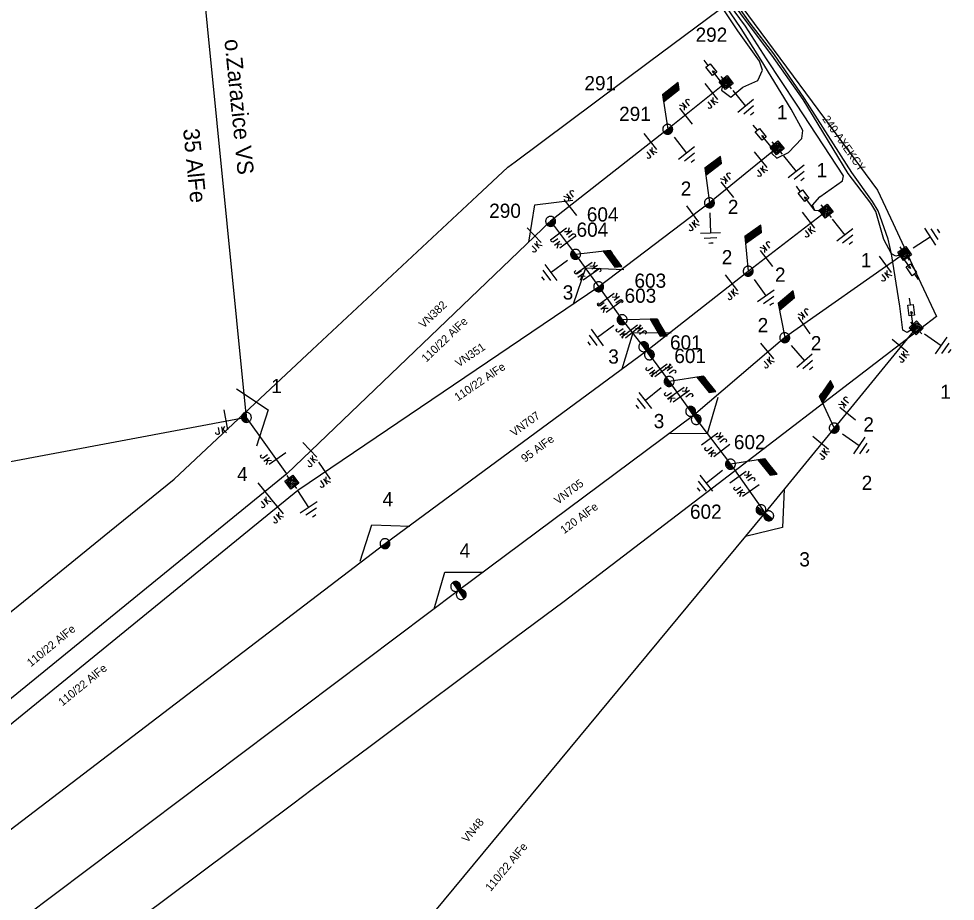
# Model space of a CAD drawing. Extents: x -545588 to -543214, y -1196037 to -1194452.
# Drawn here: x -545323.7 to -545208.3, y -1195024.5 to -1194915.7 of the extents above; entities that cross this region are included whole.
import ezdxf

# ---------------------------------------------------------------- set-up
doc = ezdxf.new("R2010")
doc.units = 0
for name, color, linetype in [('Default', 7, 'Continuous'), ('Vrstva 1', 7, 'Continuous'), ('Vrstva 11', 7, 'Continuous'), ('Vrstva 12', 7, 'Continuous'), ('Vrstva 13', 7, 'Continuous'), ('Vrstva 14', 7, 'Continuous'), ('Vrstva 15', 7, 'Continuous'), ('Vrstva 16', 7, 'Continuous'), ('Vrstva 18', 7, 'Continuous'), ('Vrstva 19', 7, 'Continuous'), ('Vrstva 2', 7, 'Continuous'), ('Vrstva 3', 7, 'Continuous'), ('Vrstva 35', 7, 'Continuous'), ('Vrstva 4', 7, 'Continuous'), ('Vrstva 5', 7, 'Continuous'), ('Vrstva 52', 7, 'Continuous'), ('Vrstva 53', 7, 'Continuous'), ('Vrstva 54', 7, 'Continuous'), ('Vrstva 6', 7, 'Continuous')]:
    doc.layers.add(name, color=color, linetype=linetype)

# ---------------------------------------------------------------- blocks, each defined once
blk = doc.blocks.new('VN840')
at = {"layer": 'Vrstva 15'}
for points in [[(-0.01, 1.41), (-0.01, -1.09)], [(-1.51, -1.24), (-1.51, -1.15)], [(-1.09, -0.59), (-1.09, -1.24)], [(-0.68, -0.59), (-0.68, -1.42)], [(-0.68, -1.11), (-0.27, -0.59)], [(-0.54, -0.94), (-0.2, -1.42)], [(-1.48, -1.35), (-1.51, -1.24)], [(-1.33, -1.42), (-1.48, -1.35)], [(-1.27, -1.42), (-1.33, -1.42)], [(-1.13, -1.35), (-1.27, -1.42)], [(-1.09, -1.24), (-1.13, -1.35)]]:
    blk.add_lwpolyline(points, dxfattribs=at)
blk = doc.blocks.new('VN860')
at = {"layer": 'Vrstva 15'}
for points in [[(-3.74, 0), (0.01, 2.82)], [(0.01, 2.82), (3.76, 0)]]:
    blk.add_lwpolyline(points, dxfattribs=at)
blk = doc.blocks.new('VN440')
at = {"layer": 'Vrstva 2'}
for points in [[(1.22, 0), (1.21, 0.13), (1.19, 0.25), (1.16, 0.38), (1.11, 0.5), (1.05, 0.61), (0.98, 0.72), (0.9, 0.82), (0.81, 0.91), (0.71, 0.99), (0.6, 1.06), (0.49, 1.12), (0.37, 1.16), (0.25, 1.2), (0.12, 1.22), (-0.01, 1.22), (-0.14, 1.22), (-0.26, 1.2), (-0.39, 1.16), (-0.51, 1.12), (-0.62, 1.06), (-0.73, 0.99), (-0.83, 0.91), (-0.92, 0.82), (-1, 0.72), (-1.07, 0.61), (-1.13, 0.5), (-1.18, 0.38), (-1.21, 0.25), (-1.23, 0.13), (-1.24, 0), (-1.23, -0.13), (-1.21, -0.26), (-1.18, -0.38), (-1.13, -0.5), (-1.07, -0.62), (-1, -0.73), (-0.92, -0.83), (-0.83, -0.92), (-0.73, -1), (-0.62, -1.07), (-0.51, -1.13), (-0.39, -1.17), (-0.26, -1.2), (-0.14, -1.23), (-0.01, -1.23), (0.12, -1.23), (0.25, -1.2), (0.37, -1.17), (0.49, -1.13), (0.6, -1.07), (0.71, -1), (0.81, -0.92), (0.9, -0.83), (0.98, -0.73), (1.05, -0.62), (1.11, -0.5), (1.16, -0.38), (1.19, -0.26), (1.21, -0.13), (1.22, 0)], [(-1.24, 0), (1.22, 0)], [(-1.18, -0.34), (1.1, -0.34)], [(-1.01, -0.63), (0.97, -0.63)], [(-0.74, -0.92), (0.68, -0.92)]]:
    blk.add_lwpolyline(points, dxfattribs=at)
blk = doc.blocks.new('VN890')
at = {"layer": 'Vrstva 4'}
for points in [[(-0.41, 0.41), (0.41, 0)], [(-0.41, -0.41), (-0.41, 0.41)], [(0.41, 0), (-0.41, -0.41)], [(-0.34, 0.31), (0.27, 0), (-0.34, -0.3), (-0.34, 0.31)], [(-0.26, 0.2), (0.1, 0), (-0.26, -0.18), (-0.26, 0.2)], [(-0.19, 0.09), (-0.04, 0), (-0.19, -0.08), (-0.19, 0.09)], [(-0.16, -0.01), (-0.16, 0.03), (-0.13, 0.01), (-0.16, -0.01)]]:
    blk.add_lwpolyline(points, dxfattribs=at)
blk = doc.blocks.new('VN820')
at = {"layer": 'Vrstva 13'}
for points in [[(0, 0), (0, -2.1)], [(-0.32, -1.63), (0.34, -1.63)], [(-0.32, -2.95), (-0.32, -1.63)], [(0, -2.1), (-0.12, -1.86)], [(0, -2.1), (0.12, -1.86)], [(0.34, -1.63), (0.34, -2.95)], [(0.34, -2.95), (-0.32, -2.95)], [(0, -2.95), (0, -3.75)]]:
    blk.add_lwpolyline(points, dxfattribs=at)
blk = doc.blocks.new('VN810')
at = {"layer": 'Vrstva 14'}
for points in [[(0, -1.25), (0, -3.75)], [(1.25, -3.75), (-1.25, -3.75)], [(0.77, -4.37), (-0.8, -4.37)], [(0, -5), (-0.25, -5)], [(0.27, -5), (0, -5)]]:
    blk.add_lwpolyline(points, dxfattribs=at)
blk = doc.blocks.new('VN450')
at = {"layer": 'Vrstva 2'}
for points in [[(0, 0), (-0.01, 0.13), (-0.03, 0.25), (-0.06, 0.38), (-0.11, 0.5), (-0.16, 0.61), (-0.23, 0.72), (-0.31, 0.82), (-0.4, 0.91), (-0.5, 0.99), (-0.61, 1.06), (-0.72, 1.11), (-0.84, 1.16), (-0.97, 1.19), (-1.09, 1.21), (-1.22, 1.22), (-1.35, 1.21), (-1.47, 1.19), (-1.59, 1.16), (-1.71, 1.11), (-1.83, 1.06), (-1.93, 0.99), (-2.03, 0.91), (-2.12, 0.82), (-2.2, 0.72), (-2.27, 0.61), (-2.33, 0.5), (-2.38, 0.38), (-2.41, 0.25), (-2.43, 0.13), (-2.44, 0), (-2.43, -0.13), (-2.41, -0.25), (-2.38, -0.38), (-2.33, -0.5), (-2.27, -0.61), (-2.2, -0.72), (-2.12, -0.82), (-2.03, -0.91), (-1.93, -0.99), (-1.83, -1.06), (-1.71, -1.11), (-1.59, -1.16), (-1.47, -1.19), (-1.35, -1.21), (-1.22, -1.22), (-1.09, -1.21), (-0.97, -1.19), (-0.84, -1.16), (-0.72, -1.11), (-0.61, -1.06), (-0.5, -0.99), (-0.4, -0.91), (-0.31, -0.82), (-0.23, -0.72), (-0.16, -0.61), (-0.11, -0.5), (-0.06, -0.38), (-0.03, -0.25), (-0.01, -0.13), (0, 0)], [(-2.44, 0), (2.44, 0)], [(2.44, 0), (2.43, 0.13), (2.41, 0.25), (2.38, 0.38), (2.33, 0.5), (2.27, 0.61), (2.2, 0.72), (2.12, 0.82), (2.03, 0.91), (1.94, 0.99), (1.83, 1.06), (1.71, 1.11), (1.6, 1.16), (1.47, 1.19), (1.35, 1.21), (1.22, 1.22), (1.09, 1.21), (0.97, 1.19), (0.84, 1.16), (0.72, 1.11), (0.61, 1.06), (0.5, 0.99), (0.4, 0.91), (0.31, 0.82), (0.23, 0.72), (0.16, 0.61), (0.11, 0.5), (0.06, 0.38), (0.03, 0.25), (0.01, 0.13), (0, 0), (0.01, -0.13), (0.03, -0.25), (0.06, -0.38), (0.11, -0.5), (0.16, -0.61), (0.23, -0.72), (0.31, -0.82), (0.4, -0.91), (0.5, -0.99), (0.61, -1.06), (0.72, -1.11), (0.84, -1.16), (0.97, -1.19), (1.09, -1.21), (1.22, -1.22), (1.35, -1.21), (1.47, -1.19), (1.6, -1.16), (1.71, -1.11), (1.83, -1.06), (1.94, -0.99), (2.03, -0.91), (2.12, -0.82), (2.2, -0.72), (2.27, -0.61), (2.33, -0.5), (2.38, -0.38), (2.41, -0.25), (2.43, -0.13), (2.44, 0)], [(-2.4, -0.31), (-0.04, -0.31)], [(-2.26, -0.61), (-0.17, -0.61)], [(-2.01, -0.92), (-0.42, -0.92)], [(0.04, -0.31), (2.4, -0.31)], [(0.17, -0.61), (2.27, -0.61)], [(0.42, -0.92), (2.02, -0.92)]]:
    blk.add_lwpolyline(points, dxfattribs=at)
blk = doc.blocks.new('VN001')
at = {"layer": 'Default'}
for p, q in [((1.99, 3.48), (4.4, 3.48)), ((2.02, 3.53), (4.43, 3.53)), ((2.05, 3.58), (4.46, 3.58)), ((2.07, 3.63), (4.49, 3.63)), ((2.1, 3.68), (4.52, 3.68)), ((2.13, 3.73), (2.54, 3.73)), ((1.73, 3.03), (4.14, 3.03)), ((1.76, 3.08), (4.17, 3.08)), ((1.79, 3.13), (4.2, 3.13)), ((1.82, 3.18), (4.23, 3.18)), ((1.85, 3.23), (4.26, 3.23)), ((1.87, 3.28), (4.29, 3.28)), ((1.9, 3.33), (4.32, 3.33)), ((1.93, 3.38), (4.35, 3.38)), ((1.96, 3.43), (4.37, 3.43))]:
    blk.add_line(p, q, dxfattribs=at)
blk.add_lwpolyline([(2.13, 3.73), (0, 0)], dxfattribs=at)
blk.add_lwpolyline([(4.55, 3.73), (2.13, 3.73), (1.7, 2.98), (4.12, 2.99)], close=True, dxfattribs=at)
blk = doc.blocks.new('VN470')
at = {"layer": 'Vrstva 2'}
for points in [[(-1.23, 1.22), (1.23, 1.22)], [(-1.23, -1.23), (-1.23, 1.22)], [(-0.92, 0.9), (0.92, 0.9)], [(-0.92, -0.95), (-0.92, 0.9)], [(-0.61, 0.61), (0.61, 0.61)], [(-0.61, -0.62), (-0.61, 0.61)], [(-0.31, -0.27), (-0.31, 0.34)], [(-0.31, 0.34), (0.31, 0.34)], [(0, 1.22), (0, 1.97)], [(0.31, 0.34), (0.31, -0.27)], [(0.61, 0.61), (0.61, -0.62)], [(0.92, 0.9), (0.92, -0.95)], [(1.23, 1.22), (1.23, -1.23)], [(1.23, -1.23), (-1.23, -1.23)], [(0.92, -0.95), (-0.92, -0.95)], [(0.61, -0.62), (-0.61, -0.62)], [(0.31, -0.27), (-0.31, -0.27)], [(0, -1.23), (0, -1.98)]]:
    blk.add_lwpolyline(points, dxfattribs=at)

msp = doc.modelspace()

# ---------------------------------------------------------------- linework, layer by layer
at = {"layer": 'Vrstva 1'}
for points in [[(-545236.49, -1194923.55), (-545243.7, -1194929.3)], [(-545243.7, -1194929.3), (-545258.13, -1194940.65)], [(-545230.22, -1194931.6), (-545238.56, -1194938.36)], [(-545238.56, -1194938.36), (-545252.21, -1194948.71)], [(-545233.78, -1194946.79), (-545224.18, -1194939.38)], [(-545258.13, -1194940.65), (-545290.64, -1194971.78)], [(-545214.51, -1194944.61), (-545229.28, -1194954.99)], [(-545246.31, -1194956.61), (-545233.78, -1194946.79)], [(-545252.21, -1194948.71), (-545289.27, -1194973.82)], [(-545213.08, -1194953.79), (-545223.18, -1194966.13)], [(-545229.28, -1194954.99), (-545240.53, -1194964.58)], [(-545395.75, -1195077.92), (-545332.4, -1195021.48), (-545278.54, -1194980.38), (-545246.31, -1194956.61)], [(-545240.53, -1194964.58), (-545269.49, -1194986.16), (-545326.84, -1195029.29), (-545358.05, -1195052.83)], [(-545223.18, -1194966.13), (-545231.73, -1194976.58)], [(-545290.64, -1194971.78), (-545405.11, -1195065.07), (-545495.54, -1195139.14), (-545571.44, -1195160.65)], [(-545289.27, -1194973.82), (-545403.67, -1195067.08), (-545494.32, -1195141.28), (-545571.32, -1195163.18)], [(-545231.73, -1194976.58), (-545288.13, -1195044.67), (-545343.3, -1195111.41), (-545397.6, -1195177.04), (-545441.95, -1195249.1), (-545485.78, -1195319.69), (-545525.23, -1195383.69), (-545557.58, -1195435.71)]]:
    msp.add_lwpolyline(points, dxfattribs=at)
at = {"layer": 'Vrstva 35'}
for points in [[(-545235.38, -1194913.06), (-545225.9, -1194925.9), (-545217.85, -1194936.81), (-545217.53, -1194937.5), (-545215.93, -1194940.93), (-545212.5, -1194948.28), (-545210.58, -1194952.4), (-545212.5, -1194953.87), (-545223.78, -1194962.5), (-545237.5, -1194972.99), (-545256.45, -1194987.5), (-545262.5, -1194992.01), (-545280.38, -1195005.38), (-545287.5, -1195010.7), (-545289.91, -1195012.5), (-545312.5, -1195029.39)], [(-545337.5, -1194999.2), (-545323.09, -1194987.5), (-545312.5, -1194978.9), (-545304.54, -1194972.43), (-545293.92, -1194962.5), (-545287.5, -1194956.5), (-545267.17, -1194937.5), (-545263.39, -1194933.97), (-545262.5, -1194933.31), (-545245.95, -1194920.95), (-545237.5, -1194914.64)]]:
    msp.add_lwpolyline(points, dxfattribs=at)
at = {"layer": 'Vrstva 5'}
for points in [[(-545236.49, -1194923.55), (-545236.72, -1194923.58), (-545236.89, -1194923.73), (-545237.09, -1194924.48), (-545235.92, -1194925.33), (-545234.43, -1194924.11), (-545232.58, -1194923.3), (-545232.02, -1194922.01), (-545232.39, -1194920.91), (-545235.07, -1194917.17), (-545239.41, -1194910.6)], [(-545230.22, -1194931.6), (-545230.61, -1194931.66), (-545230.78, -1194931.68), (-545230.86, -1194932.28), (-545230.25, -1194932.87), (-545228.8, -1194932.18), (-545227.16, -1194930.44), (-545227.04, -1194929.44), (-545228.49, -1194926.82), (-545232.2, -1194920.78), (-545234.65, -1194916.87), (-545239.05, -1194910.4)], [(-545224.18, -1194939.38), (-545224.73, -1194939.37), (-545225.56, -1194939.3), (-545225.86, -1194938.67), (-545224.97, -1194937.65), (-545222.16, -1194935.67), (-545222.02, -1194935.04), (-545227.82, -1194926.2), (-545231.53, -1194920.6), (-545234.13, -1194916.6), (-545238.74, -1194910.26)], [(-545214.51, -1194944.61), (-545214.64, -1194944.43), (-545214.85, -1194944.63), (-545215, -1194944.76), (-545215.59, -1194944.96), (-545216.14, -1194944.67), (-545217.09, -1194942.9), (-545218.06, -1194939.43), (-545218.69, -1194938.4), (-545221.46, -1194934.77), (-545227.03, -1194925.62), (-545230.86, -1194920.16), (-545233.75, -1194916.35), (-545238.35, -1194910.11)], [(-545213.08, -1194953.79), (-545213.42, -1194953.86), (-545214.2, -1194954.37), (-545214.73, -1194954.07), (-545215.11, -1194951.12), (-545216.14, -1194944.67), (-545216.55, -1194942.85), (-545217.78, -1194939.34), (-545218.48, -1194938.21), (-545221.01, -1194934.62), (-545226.84, -1194925.51), (-545230.61, -1194920), (-545233.55, -1194916.21), (-545237.86, -1194910.11)]]:
    msp.add_lwpolyline(points, dxfattribs=at)
at = {"layer": 'Vrstva 52'}
for points in [[(-545295.62, -1194964.82), (-545301.62, -1194904.6), (-545302.55, -1194903.99), (-545302.62, -1194901.45), (-545318.54, -1194873.42)], [(-545258.13, -1194940.65), (-545255.05, -1194944.72)], [(-545255.05, -1194944.72), (-545252.21, -1194948.71)], [(-545252.21, -1194948.71), (-545249.31, -1194952.78)], [(-545249.31, -1194952.78), (-545246.31, -1194956.61)], [(-545246.31, -1194956.61), (-545243.52, -1194960.39)], [(-545243.52, -1194960.39), (-545240.53, -1194964.58)], [(-545295.62, -1194964.82), (-545381.37, -1194980.94), (-545453.74, -1194986.07), (-545493.42, -1194989.16)], [(-545290.64, -1194971.78), (-545295.62, -1194964.82)], [(-545240.53, -1194964.58), (-545235.97, -1194970.59)], [(-545235.97, -1194970.59), (-545231.73, -1194976.58)]]:
    msp.add_lwpolyline(points, dxfattribs=at)

# ---------------------------------------------------------------- block references
at = {"layer": 'Vrstva 11'}
for p, rotation in [((-545243.7, -1194929.3), 38.18679450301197), ((-545238.56, -1194938.36), 37.17218889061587), ((-545233.78, -1194946.79), 35.223016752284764), ((-545255.05, -1194944.72), -54.047736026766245), ((-545229.28, -1194954.99), 40.44745010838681), ((-545249.31, -1194952.78), -59.175191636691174), ((-545243.52, -1194960.39), -51.362411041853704), ((-545223.18, -1194966.13), 55.0153638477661), ((-545235.97, -1194970.59), -51.52944450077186)]:
    msp.add_blockref('VN001', p, dxfattribs=dict(at, rotation=rotation))
at = {"layer": 'Vrstva 13'}
for name, p, xscale, yscale, rotation in [('VN470', (-545236.49, -1194923.55), 0.5000000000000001, 0.5, 38.57166112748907), ('VN440', (-545243.7, -1194929.3), 0.5, 0.5, 38.18600550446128), ('VN470', (-545230.22, -1194931.6), 0.5, 0.5000000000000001, 39.025683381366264), ('VN440', (-545238.56, -1194938.36), 0.5, 0.49999999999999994, 34.95319163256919), ('VN470', (-545224.18, -1194939.38), 0.5, 0.5000000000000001, 37.661386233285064), ('VN440', (-545258.13, -1194940.65), 0.5, 0.5, 35.95226383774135), ('VN440', (-545255.05, -1194944.72), 0.5, 0.5, -53.39277781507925), ('VN470', (-545214.51, -1194944.61), 0.5, 0.5, 35.09740273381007), ('VN440', (-545233.78, -1194946.79), 0.5, 0.5000000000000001, 35.223016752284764), ('VN440', (-545252.21, -1194948.71), 0.5, 0.5, 35.95226383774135), ('VN440', (-545249.31, -1194952.78), 0.5, 0.5, -54.273602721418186), ('VN470', (-545213.08, -1194953.79), 0.5, 0.49999999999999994, 43.663602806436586), ('VN440', (-545229.28, -1194954.99), 0.5, 0.5, 40.44745010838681), ('VN450', (-545246.31, -1194956.61), 0.5, 0.5, 125.22301671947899), ('VN440', (-545243.52, -1194960.39), 0.5, 0.49999999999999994, -51.362411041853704), ('VN450', (-545240.53, -1194964.58), 0.5, 0.5000000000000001, 124.71140835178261), ('VN440', (-545295.62, -1194964.82), 0.5, 0.5, -84.30825828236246), ('VN440', (-545223.18, -1194966.13), 0.5, 0.5, 50.71019441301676), ('VN440', (-545235.97, -1194970.59), 0.5, 0.5, -54.644949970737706), ('VN470', (-545290.02, -1194972.8), 0.5, 0.5, 35.95226383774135), ('VN450', (-545231.73, -1194976.58), 0.5, 0.4999999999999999, -38.48263617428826), ('VN440', (-545278.54, -1194980.38), 0.49999999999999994, 0.5000000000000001, 35.22301664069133), ('VN450', (-545269.49, -1194986.16), 0.49999999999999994, 0.5, 124.71140827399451)]:
    msp.add_blockref(name, p, dxfattribs=dict(at, xscale=xscale, yscale=yscale, rotation=rotation))
at = {"layer": 'Vrstva 15'}
for p, rotation in [((-545236.49, -1194923.55), 39.57557080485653), ((-545243.7, -1194929.3), 38.18696673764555), ((-545230.22, -1194931.6), 38.759191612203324), ((-545238.56, -1194938.36), 1.9926267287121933), ((-545224.18, -1194939.38), 37.66631396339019), ((-545214.51, -1194944.61), 123.37775649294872), ((-545255.05, -1194944.72), -53.40005286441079), ((-545233.78, -1194946.79), 35.223016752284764), ((-545249.31, -1194952.78), -54.27577217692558), ((-545213.08, -1194953.79), 55.019999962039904), ((-545229.28, -1194954.99), 40.4480305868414), ((-545243.52, -1194960.39), -51.35691383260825), ((-545223.18, -1194966.13), 55.0153639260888), ((-545235.97, -1194970.59), -51.52944450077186), ((-545290.02, -1194972.8), 33.3588583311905)]:
    msp.add_blockref('VN810', p, dxfattribs=dict(at, rotation=rotation))
at = {"layer": 'Vrstva 16'}
for p, rotation in [((-545236.89, -1194923.73), -141.52061114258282), ((-545230.78, -1194931.68), -140.71454174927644), ((-545225.56, -1194939.3), -142.37886389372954), ((-545215, -1194944.76), 35.09724162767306), ((-545213.42, -1194953.86), -172.82982508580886)]:
    msp.add_blockref('VN820', p, dxfattribs=dict(at, rotation=rotation))
at = {"layer": 'Vrstva 18'}
for name, p, rotation in [('VN840', (-545238.24, -1194924.77), 37.809900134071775), ('VN840', (-545241.52, -1194927.56), -141.42955829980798), ('VN840', (-545245.77, -1194930.93), 38.18633062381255), ('VN840', (-545232.15, -1194933.16), 39.020663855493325), ('VN840', (-545236.44, -1194936.64), -140.97279439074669), ('VN860', (-545258.13, -1194940.65), 43.75872502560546), ('VN840', (-545255.79, -1194938.81), -141.81291385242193), ('VN840', (-545240.54, -1194939.86), 37.16967780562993), ('VN840', (-545226.25, -1194940.64), 37.484938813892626), ('VN840', (-545260.03, -1194942.47), 43.759150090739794), ('VN840', (-545257.04, -1194942.09), 127.11686113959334), ('VN840', (-545256.12, -1194943.31), -52.88313888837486), ('VN840', (-545231.61, -1194945.11), -142.3361888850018), ('VN860', (-545252.21, -1194948.71), 34.11712501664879), ('VN840', (-545253.22, -1194947.29), -54.55751941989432), ('VN840', (-545253.92, -1194946.31), 125.44248060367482), ('VN840', (-545216.8, -1194946.07), 37.15255827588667), ('VN840', (-545235.76, -1194948.34), 38.29414440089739), ('VN840', (-545250.4, -1194951.25), -54.52896109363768), ('VN840', (-545251.19, -1194950.14), 125.47103896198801), ('VN840', (-545226.98, -1194953.38), -144.89947772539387), ('VN860', (-545246.31, -1194956.61), 36.40879723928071), ('VN840', (-545248.06, -1194954.38), -51.92876399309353), ('VN840', (-545248.3, -1194954.07), 128.07123606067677), ('VN840', (-545231.35, -1194956.75), 40.44653339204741), ('VN840', (-545214.94, -1194956.06), 50.7004805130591), ('VN840', (-545244.41, -1194959.19), -53.56914167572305), ('VN840', (-545244.66, -1194958.85), 126.430858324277), ('VN860', (-545295.62, -1194964.82), -70.65378887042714), ('VN840', (-545242.14, -1194962.33), -54.48819997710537), ('VN840', (-545242.57, -1194961.72), 125.51179994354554), ('VN860', (-545240.53, -1194964.58), -143.3872638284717), ('VN840', (-545221.67, -1194964.28), -129.2995194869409), ('VN840', (-545298.13, -1194965.29), 10.64668321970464), ('VN840', (-545238.42, -1194967.36), 127.18888063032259), ('VN840', (-545237.15, -1194969.04), -52.811119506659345), ('VN840', (-545224.72, -1194968.02), 50.71059436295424), ('VN840', (-545291.91, -1194970), -54.584030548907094), ('VN840', (-545287.69, -1194968.92), 44.07588337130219), ('VN840', (-545285.91, -1194971.51), 34.4793945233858), ('VN840', (-545234.92, -1194972.07), 125.29263057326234), ('VN840', (-545233.58, -1194973.97), -54.70736942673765), ('VN840', (-545293.33, -1194973.98), 39.18124444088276), ('VN860', (-545231.73, -1194976.58), -129.28824718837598), ('VN840', (-545291.79, -1194975.87), 39.189741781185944), ('VN860', (-545278.54, -1194980.38), 35.22301664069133), ('VN860', (-545269.49, -1194986.16), 36.89043607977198)]:
    msp.add_blockref(name, p, dxfattribs=dict(at, rotation=rotation))
at = {"layer": 'Vrstva 19'}
for p, rotation in [((-545236.72, -1194923.58), -141.34019170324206), ((-545230.61, -1194931.66), -171.49811939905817), ((-545224.73, -1194939.37), 178.8509611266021), ((-545214.85, -1194944.63), -137.48955276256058), ((-545213.42, -1194953.86), -134.2361027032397)]:
    msp.add_blockref('VN890', p, dxfattribs=dict(at, rotation=rotation))

# ---------------------------------------------------------------- texts
at = {"layer": 'Vrstva 12'}
for s, p in [('291', (-545253.97, -1194924.49)), ('2', (-545236.29, -1194939.75)), ('604', (-545254.94, -1194942.55)), ('2', (-545230.49, -1194948.1)), ('603', (-545249.02, -1194950.69)), ('2', (-545226.07, -1194956.55)), ('601', (-545242.89, -1194958.12)), ('2', (-545219.59, -1194966.56)), ('602', (-545235.55, -1194968.74))]:
    msp.add_text(s, height=1.75, dxfattribs=at).set_placement(p)
at = {"layer": 'Vrstva 14'}
for s, p in [('292', (-545240.27, -1194918.52)), ('291', (-545249.69, -1194928.28)), ('1', (-545230.25, -1194928.08)), ('1', (-545225.36, -1194935.22)), ('2', (-545242.1, -1194937.49)), ('290', (-545265.7, -1194940.22)), ('604', (-545253.67, -1194940.67)), ('2', (-545237.04, -1194945.94)), ('1', (-545219.91, -1194946.32)), ('603', (-545247.8, -1194948.84)), ('3', (-545256.64, -1194950.29)), ('2', (-545232.62, -1194954.32)), ('601', (-545243.42, -1194956.45)), ('3', (-545251.03, -1194958.19)), ('1', (-545292.56, -1194961.82)), ('1', (-545210.11, -1194962.53)), ('3', (-545245.43, -1194966.15)), ('4', (-545296.76, -1194972.68)), ('2', (-545219.8, -1194973.76)), ('4', (-545278.85, -1194975.78)), ('602', (-545240.96, -1194977.32)), ('4', (-545269.35, -1194982.11)), ('3', (-545227.48, -1194983.19))]:
    msp.add_text(s, height=1.75, dxfattribs=at).set_placement(p)
at = {"layer": 'Vrstva 2'}
for s, rotation, p in [('110/22 AlFe', 43.759, (-545273.46, -1194958.08)), ('110/22 AlFe', 34.117, (-545269.57, -1194962.86)), ('95 AlFe', 36.409, (-545261.31, -1194970.43)), ('120 AlFe', 36.692, (-545256.47, -1194979.23)), ('110/22 AlFe', 39.181, (-545322.17, -1194995.62)), ('110/22 AlFe', 39.19, (-545318.29, -1195000.46)), ('110/22 AlFe', 50.365, (-545265.51, -1195023.32))]:
    msp.add_text(s, height=1, rotation=rotation, dxfattribs=at).set_placement(p)
at = {"layer": 'Vrstva 3'}
for s, rotation, p in [('VN382', 43.759, (-545273.79, -1194953.9)), ('VN351', 34.117, (-545269.46, -1194958.68)), ('VN707', 36.409, (-545262.63, -1194967.24)), ('VN705', 36.692, (-545257.24, -1194975.6)), ('VN48', 50.365, (-545268.41, -1195017.32))]:
    msp.add_text(s, height=1, rotation=rotation, dxfattribs=at).set_placement(p)
at = {"layer": 'Vrstva 53'}
msp.add_text('35 AlFe', height=2, rotation=275.692, dxfattribs=at).set_placement((-545303.43, -1194929.29))
at = {"layer": 'Vrstva 54'}
msp.add_text('o.Zarazice VS', height=2, rotation=275.692, dxfattribs=at).set_placement((-545298.34, -1194918.27))
at = {"layer": 'Vrstva 6'}
msp.add_text('240 AXEKCY', height=1, rotation=305.174, dxfattribs=at).set_placement((-545224.7, -1194928.04))

doc.saveas('drawing.dxf')
